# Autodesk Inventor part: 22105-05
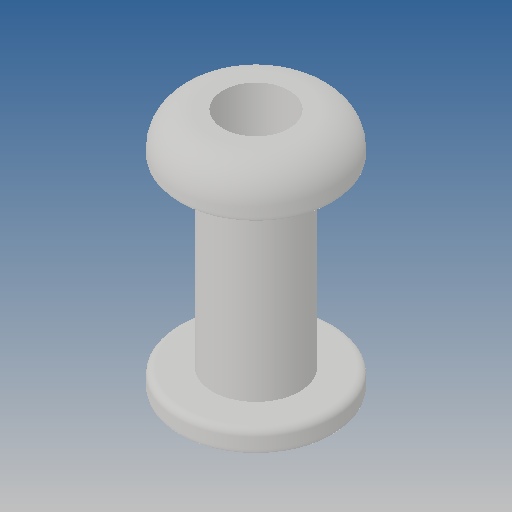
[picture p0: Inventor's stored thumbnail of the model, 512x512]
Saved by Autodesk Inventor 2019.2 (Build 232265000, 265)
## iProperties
Created: 2017-06
Part Number: 22105-05
Material: Ogólny
Document SubType Name: Modeling
Designer: CADENGINEERING4
Density: 1 g/cm^3
Appearance: Domyślna
Author: CADENGINEERING4
Revision Number: ÈÎºÎ
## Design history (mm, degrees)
feature "Ðý×ª1"
node "Bryła1"
